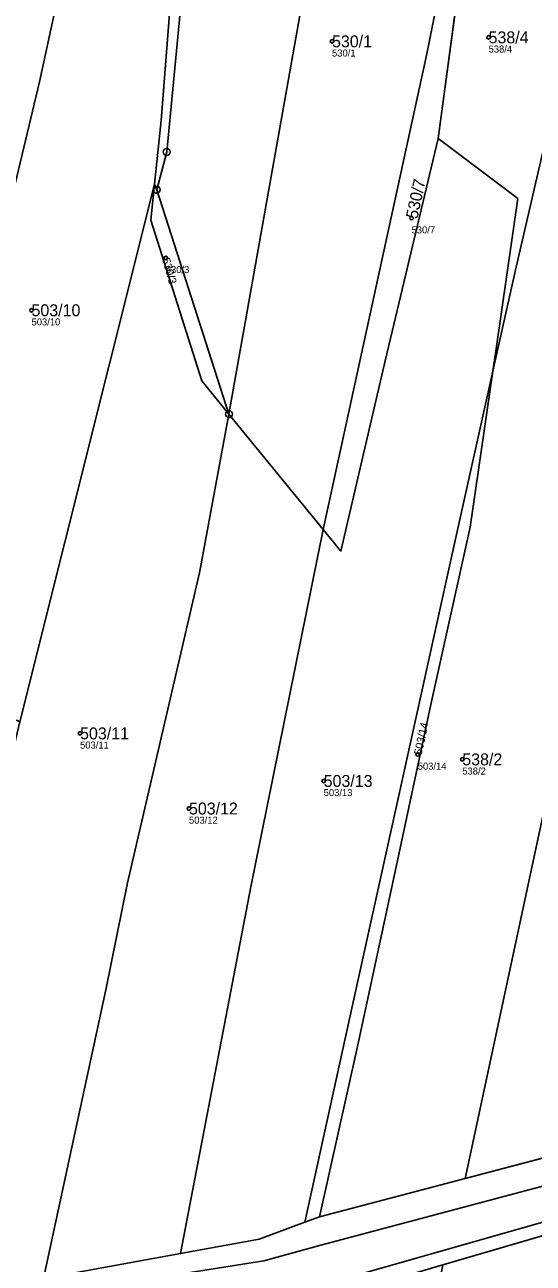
# Model space of a CAD drawing. Extents: x -732749 to -730903, y -1025757 to -1023435.
# Drawn here: x -731715.5 to -731643.2, y -1024715.4 to -1024539 of the extents above; entities that cross this region are included whole.
import ezdxf

# ---------------------------------------------------------------- set-up
doc = ezdxf.new("R2010")
doc.units = 0
for name, color, linetype in [('Definiční body', 7, 'Continuous'), ('Hranice parcel', 7, 'Continuous'), ('Parcelní čísla', 7, 'Continuous'), ('Polygon parcely', 7, 'Continuous'), ('Vnitřní kresba', 7, 'Continuous'), ('Značky bodu BP', 7, 'Continuous')]:
    doc.layers.add(name, color=color, linetype=linetype)

msp = doc.modelspace()

# ---------------------------------------------------------------- linework, layer by layer
at = {"layer": 'Definiční body'}
for centre in [(-731671.83, -1024541.34), (-731649.56, -1024540.77), (-731660.52, -1024566.53), (-731695.48, -1024572.19), (-731714.58, -1024579.64), (-731707.67, -1024639.91), (-731659.64, -1024642.92), (-731653.3, -1024643.61), (-731673.02, -1024646.68), (-731692.18, -1024650.61)]:
    msp.add_circle(centre, 0.25, dxfattribs=at)
at = {"layer": 'Hranice parcel'}
for p, q in [((-731686.49, -1024594.44), (-731666.53, -1024482.14)), ((-731656.73, -1024555.17), (-731650.19, -1024506.59)), ((-731696.14, -1024552.61), (-731693.69, -1024520.94)), ((-731697.08, -1024561.67), (-731696.14, -1024552.61)), ((-731716.24, -1024638.26), (-731697.08, -1024561.67)), ((-731697.62, -1024566.81), (-731697.08, -1024561.67)), ((-731696.77, -1024562.48), (-731697.08, -1024561.67)), ((-731696.77, -1024562.48), (-731686.49, -1024594.44)), ((-731686.49, -1024594.44), (-731673.09, -1024610.86)), ((-731629.2, -1024697.06), (-731652.88, -1024703.31)), ((-731673.59, -1024708.77), (-731652.88, -1024703.31)), ((-731673.59, -1024708.77), (-731675.68, -1024709.54)), ((-731656.05, -1024715.62), (-731632.15, -1024708.61)), ((-731675.68, -1024709.54), (-731682.19, -1024711.95)), ((-731682.19, -1024711.95), (-731693.38, -1024713.99)), ((-731693.38, -1024713.99), (-731712.87, -1024717.54))]:
    msp.add_line(p, q, dxfattribs=at)
for points in [[(-731686.96, -1024469.17), (-731695.35, -1024557.09), (-731696.77, -1024562.48)], [(-731673.09, -1024610.86), (-731658.36, -1024543.11), (-731650.78, -1024505.11)], [(-731734.05, -1024633.47), (-731713.45, -1024547.12), (-731707.13, -1024517.89)], [(-731639.82, -1024548.26), (-731645.79, -1024574.11), (-731648.95, -1024588.3)], [(-731656.73, -1024555.17), (-731664.27, -1024586.86), (-731670.56, -1024613.95), (-731673.09, -1024610.86)], [(-731648.95, -1024588.3), (-731648.54, -1024585.48), (-731645.4, -1024563.74), (-731653.71, -1024557.46), (-731656.73, -1024555.17)], [(-731652.88, -1024703.31), (-731639.56, -1024641.06), (-731622.62, -1024565.19)], [(-731686.49, -1024594.44), (-731690.35, -1024589.71), (-731697.62, -1024566.81)], [(-731675.68, -1024709.54), (-731668.94, -1024678.63), (-731654.51, -1024613.27), (-731648.95, -1024588.3)], [(-731648.95, -1024588.3), (-731652.18, -1024610.53), (-731657.78, -1024635.81), (-731662.99, -1024660.26), (-731668.32, -1024684.91), (-731673.59, -1024708.77)], [(-731712.87, -1024717.54), (-731703.99, -1024676.41), (-731700.91, -1024661.18), (-731690.7, -1024617.06), (-731686.49, -1024594.44)], [(-731693.38, -1024713.99), (-731683.36, -1024661.75), (-731673.09, -1024610.86)]]:
    msp.add_lwpolyline(points, dxfattribs=at)
at = {"layer": 'Polygon parcely'}
for points in [[(-731687.01, -1024469.13), (-731693.69, -1024520.94), (-731696.14, -1024552.61), (-731697.08, -1024561.67), (-731696.77, -1024562.48), (-731695.35, -1024557.09), (-731686.96, -1024469.17)], [(-731695.35, -1024557.09), (-731696.77, -1024562.48), (-731686.49, -1024594.44), (-731666.53, -1024482.14), (-731686.96, -1024469.17)], [(-731658.36, -1024543.11), (-731650.78, -1024505.11), (-731654.37, -1024496.11), (-731654.91, -1024494.76), (-731666.53, -1024482.14), (-731686.49, -1024594.44), (-731673.09, -1024610.86)], [(-731707.13, -1024517.89), (-731743.44, -1024501.87), (-731759.7, -1024496.71), (-731787.4, -1024607.01), (-731752.45, -1024614.47), (-731732.6, -1024618.66), (-731734.11, -1024625.8), (-731735.24, -1024629.79), (-731736, -1024632.96), (-731734.05, -1024633.47), (-731713.45, -1024547.12)], [(-731656.73, -1024555.17), (-731650.19, -1024506.59), (-731650.78, -1024505.11), (-731658.36, -1024543.11), (-731673.09, -1024610.86), (-731670.56, -1024613.95), (-731664.27, -1024586.86)], [(-731637.02, -1024537.04), (-731643.32, -1024523.8), (-731650.19, -1024506.59), (-731656.73, -1024555.17), (-731653.71, -1024557.46), (-731645.4, -1024563.74), (-731648.54, -1024585.48), (-731648.95, -1024588.3), (-731645.79, -1024574.11), (-731639.82, -1024548.26)], [(-731693.69, -1024520.94), (-731707.13, -1024517.89), (-731713.45, -1024547.12), (-731734.05, -1024633.47), (-731716.63, -1024638.06), (-731716.24, -1024638.26), (-731697.08, -1024561.67), (-731696.14, -1024552.61)], [(-731652.18, -1024610.53), (-731657.78, -1024635.81), (-731662.99, -1024660.26), (-731668.32, -1024684.91), (-731673.59, -1024708.77), (-731652.88, -1024703.31), (-731639.56, -1024641.06), (-731622.62, -1024565.19), (-731639.82, -1024548.26), (-731645.79, -1024574.11), (-731648.95, -1024588.3)], [(-731653.71, -1024557.46), (-731656.73, -1024555.17), (-731664.27, -1024586.86), (-731670.56, -1024613.95), (-731673.09, -1024610.86), (-731683.36, -1024661.75), (-731693.38, -1024713.99), (-731682.19, -1024711.95), (-731675.68, -1024709.54), (-731668.94, -1024678.63), (-731654.51, -1024613.27), (-731648.95, -1024588.3), (-731648.54, -1024585.48), (-731645.4, -1024563.74)], [(-731700.91, -1024661.18), (-731690.7, -1024617.06), (-731686.49, -1024594.44), (-731690.35, -1024589.71), (-731697.62, -1024566.81), (-731697.08, -1024561.67), (-731716.24, -1024638.26), (-731721.46, -1024660.27), (-731734.72, -1024716.19), (-731734.73, -1024717.58), (-731725.81, -1024718.32), (-731716.2, -1024718.15), (-731712.87, -1024717.54), (-731703.99, -1024676.41)], [(-731697.08, -1024561.67), (-731697.62, -1024566.81), (-731690.35, -1024589.71), (-731686.49, -1024594.44), (-731696.77, -1024562.48)], [(-731623.62, -1024670.48), (-731611.05, -1024614.5), (-731604.66, -1024588.27), (-731611.87, -1024575.98), (-731612.44, -1024575.22), (-731622.62, -1024565.19), (-731639.56, -1024641.06), (-731652.88, -1024703.31), (-731629.2, -1024697.06)], [(-731673.59, -1024708.77), (-731668.32, -1024684.91), (-731662.99, -1024660.26), (-731657.78, -1024635.81), (-731652.18, -1024610.53), (-731648.95, -1024588.3), (-731654.51, -1024613.27), (-731668.94, -1024678.63), (-731675.68, -1024709.54)], [(-731673.09, -1024610.86), (-731686.49, -1024594.44), (-731690.7, -1024617.06), (-731700.91, -1024661.18), (-731703.99, -1024676.41), (-731712.87, -1024717.54), (-731693.38, -1024713.99), (-731683.36, -1024661.75)], [(-731632.15, -1024708.61), (-731656.05, -1024715.62), (-731659.94, -1024736.11), (-731635.53, -1024721.73), (-731635.03, -1024718.71), (-731633.78, -1024717.9)]]:
    msp.add_lwpolyline(points, close=True, dxfattribs=at)
for points in [[(-731871.94, -1024704.58), (-731848.74, -1024708.14), (-731818.76, -1024713.7), (-731817.18, -1024713.99), (-731802.51, -1024716.71), (-731776.36, -1024721.56), (-731758.61, -1024724.28), (-731736.42, -1024726.85), (-731735.52, -1024726.95), (-731725.69, -1024728.13), (-731715.7, -1024727.77), (-731714.93, -1024727.68), (-731702.01, -1024726.11), (-731696.25, -1024725.2), (-731679.89, -1024722.61), (-731656.05, -1024715.62), (-731632.15, -1024708.61), (-731608.6, -1024701.7), (-731597.31, -1024698.27), (-731589.41, -1024695.81), (-731585.06, -1024694.46), (-731546.56, -1024682.43)], [(-731629.2, -1024697.06), (-731652.88, -1024703.31), (-731673.59, -1024708.77), (-731675.68, -1024709.54), (-731682.19, -1024711.95), (-731693.38, -1024713.99), (-731712.87, -1024717.54), (-731716.2, -1024718.15), (-731725.81, -1024718.32), (-731734.73, -1024717.58), (-731756.39, -1024715.13), (-731772.49, -1024712.49), (-731778.2, -1024712.2)]]:
    msp.add_lwpolyline(points, dxfattribs=at)
at = {"layer": 'Vnitřní kresba'}
for p, q in [((-731673.42, -1024712.81), (-731638.52, -1024703.49)), ((-731680.24, -1024720.44), (-731637.27, -1024708.19)), ((-731681.53, -1024715.05), (-731673.42, -1024712.81)), ((-731716.38, -1024720.52), (-731681.53, -1024715.05))]:
    msp.add_line(p, q, dxfattribs=at)
at = {"layer": 'Značky bodu BP'}
for centre, radius in [((-731695.35, -1024557.09), 0.5), ((-731695.35, -1024557.09), 0.0303), ((-731696.77, -1024562.48), 0.5), ((-731696.77, -1024562.48), 0.0303), ((-731686.49, -1024594.44), 0.5), ((-731686.49, -1024594.44), 0.0303)]:
    msp.add_circle(centre, radius, dxfattribs=at)

# ---------------------------------------------------------------- texts
at = {"layer": 'Definiční body'}
for s, p in [('530/1', (-731671.83, -1024543.5)), ('538/4', (-731649.56, -1024542.93)), ('530/7', (-731660.52, -1024568.69)), ('530/3', (-731695.48, -1024574.35)), ('503/10', (-731714.58, -1024581.8)), ('503/11', (-731707.67, -1024642.07)), ('503/14', (-731659.64, -1024645.08)), ('538/2', (-731653.3, -1024645.77)), ('503/13', (-731673.02, -1024648.84)), ('503/12', (-731692.18, -1024652.77))]:
    msp.add_text(s, height=1, dxfattribs=at).set_placement(p)
at = {"layer": 'Parcelní čísla'}
for s, p in [('530/1', (-731671.83, -1024542.19)), ('538/4', (-731649.56, -1024541.62)), ('503/10', (-731714.58, -1024580.49)), ('503/11', (-731707.67, -1024640.76)), ('538/2', (-731653.3, -1024644.46)), ('503/13', (-731673.02, -1024647.53)), ('503/12', (-731692.18, -1024651.46))]:
    msp.add_text(s, height=1.7, dxfattribs=at).set_placement(p)
for s, height, rotation, p in [('530/7', 1.7, 78, (-731659.69, -1024566.71)), ('530/3', 1.14, 286, (-731696.03, -1024572.35)), ('503/14', 1.14, 78, (-731659.08, -1024643.04))]:
    msp.add_text(s, height=height, rotation=rotation, dxfattribs=at).set_placement(p)

doc.saveas('drawing.dxf')
